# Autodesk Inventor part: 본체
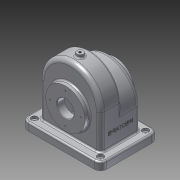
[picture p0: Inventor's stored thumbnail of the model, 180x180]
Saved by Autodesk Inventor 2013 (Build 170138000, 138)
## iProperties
Created: 2017-11
Part Number: 본체
Material: 알루미늄 6061
Document SubType Name: Modeling
Designer: Administrator
Density: 2.71 g/cm^3
Mass: 1117.61 g
Surface Area: 1185.63 cm^2
Volume: 412.401 cm^3
Author: Administrator
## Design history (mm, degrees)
sketch "스케치1"
  geometry: L1 (-58, 0)-(-58, -65); L2 (58, 0)-(58, -65); L3 (-58, -65)-(58, -65); A1 r 58 centre (0, 0) between (58, 0) and (-58, 0); 1 further point
  constraints: 6 end point, 2 point on circle, 2 tangent, 1 centre point, 1 coincident, 1 parallel, 1 vertical
  dimensions: "d0" = 116 diameter of A1; "d2" = 65 distance of L1.start L1.end; "d3" = 65 distance of L2.start L2.end
extrude "돌출1" new body sketch "스케치1" stored distance "d4" = 38; taper "d5" = 0 deg
sketch "스케치2"
  geometry: L1 (-58, -23)-(-58, -65); L2 (58, -23)-(58, -65); L3 (-58, -65)-(58, -65); L4 (-58, -65)-(58, -65) reference; A1 r 58 centre (0, 0) between (58, 0) and (-58, 0) reference; A2 r 58 centre (0, -23) between (58, -23) and (-58, -23); 1 further point
  constraints: 6 end point, 2 point on circle, 2 tangent, 1 centre point, 1 collinear, 1 parallel, 1 perpendicular, 1 vertical, 1 vertical alignment
  dimensions: "d6" = 116 diameter of A2; "d7" = 42 distance of L1.start L1.end
extrude "돌출2" join sketch "스케치2" distance "d8" = 38; taper "d9" = 0 deg
sketch "스케치3"
  geometry: L1 (-58, -65)-(58, -65) reference; C1 r 37.5 at (0, -15); 1 further point
  constraints: 1 centre point, 1 vertical alignment
  dimensions: "d10" = 75 diameter of C1; "d11" = 50 distance from line of C1.centre L1
feature "쉘1" dims "d12" = 5
extrude "돌출3" join sketch "스케치3" distance "d13" = 9; taper "d14" = 0 deg
sketch "스케치4"
  geometry: C1 r 37.5 at (0, -15) reference; 1 further point
extrude "돌출4" join sketch "스케치4" distance "d15" = 10; taper "d16" = 0 deg
sketch "스케치5"
  geometry: C1 r 16 at (0, 0); C2 r 37.5 at (0, 0) reference; 1 further point
  constraints: 1 centre point, 1 concentric
  dimensions: "d17" = 32 diameter of C1
extrude "돌출5" cut sketch "스케치5" stored distance "d18" = 10; taper "d19" = 0 deg
sketch "스케치6"
  geometry: C1 r 16 at (0, 0) reference; 2 further points
  constraints: 1 vertical alignment
  dimensions: "d20" = 29 distance of C1.centre point (0, 29)
hole "구멍1" sketch "스케치6" at (0, 29) diameter "d21" = 2.459; stored, may be unused: countersink angle "d25" = 90 deg, drill point angle "d27" = 118 deg; dims "d22" = 6, "d23" = 4, "d24" = 2, "d26" = 8
node "작업 평면1"
node "작업 평면3"
  node "작업 평면2"
sketch "스케치7"
  geometry: C1 r 6 at (0, 0); 1 further point
  constraints: 1 centre point, 1 coincident
  dimensions: "d32" = 12 diameter of C1
extrude "돌출6" join sketch "스케치7" stored distance "d34" = 10; taper "d35" = 0 deg
sketch "스케치8"
  geometry: 2 further points
  constraints: 1 coincident
hole "구멍2" sketch "스케치8" at (0, 0) diameter "d36" = 4.459; stored, may be unused: countersink angle "d40" = 90 deg, drill point angle "d42" = 118 deg; dims "d37" = 20, "d38" = 4, "d39" = 2, "d41" = 8
sketch "스케치9"
  geometry: L1 (-17, 17)-(133, 17); L2 (133, 17)-(133, -93); L3 (133, -93)-(-17, -93); L4 (-17, -93)-(-17, 17); L5 (0, 0)-(116, 0) reference; L6 (0, -76)-(0, 0) reference; L7 (116, -76)-(116, 0) reference; L8 (116, -76)-(0, -76) reference; L9 (111, -33)-(5, -33) reference; L10 (116, -38)-(0, -38) reference; 1 further point
  constraints: 8 end point, 2 parallel, 1 horizontal, 1 perpendicular
  dimensions: "d43" = 110 distance of L1.end L2.end; "d45" = 150 distance of L1.start L1.end; "d47" = 55 distance between parallel lines of L10 L1; "d48" = 75 distance from line of L4 point (58, -19)
extrude "돌출7" join sketch "스케치9" distance "d49" = 15; taper "d50" = 0 deg
fillet "모깎기1" dims "d51" = 12
sketch "스케치10"
  geometry: A1 r 12 centre (-5, 81) between (-5, 93) and (-17, 81) reference; A2 r 12 centre (121, 81) between (133, 81) and (121, 93) reference; A3 r 12 centre (121, 81) between (133, 81) and (121, 93) reference; A4 r 12 centre (121, -5) between (121, -17) and (133, -5) reference; A5 r 12 centre (121, -5) between (121, -17) and (133, -5) reference; A6 r 12 centre (-5, -5) between (-17, -5) and (-5, -17) reference; 5 further points
  constraints: 4 coincident
hole "구멍3" sketch "스케치10" at (-5, 81), (-5, -5), (121, -5), (121, 81) diameter "d52" = 5; stored, may be unused: countersink angle "d56" = 90 deg, drill point angle "d58" = 118 deg; dims "d53" = 6, "d54" = 12, "d55" = 5, "d57" = 8
fillet "모깎기2" dims "d59" = 3
sketch "스케치11"
  geometry: L1 (111, -8)-(111, -68) reference; L2 (108, -71)-(8, -71) reference; L3 (5, -68)-(5, -8) reference; L4 (8, -5)-(108, -5) reference; L5 (116, -76)-(116, 0) reference; L6 (0, 0)-(116, 0) reference; L7 (0, -76)-(0, 0) reference; L8 (116, -76)-(0, -76) reference; A1 r 3 centre (108, -68) between (108, -71) and (111, -68) reference; A2 r 3 centre (8, -68) between (5, -68) and (8, -71) reference; A3 r 3 centre (8, -8) between (8, -5) and (5, -8) reference; A4 r 3 centre (108, -8) between (111, -8) and (108, -5) reference; 1 further point
extrude "돌출8" join sketch "스케치11" distance "d60" = 15; taper "d61" = 0 deg
fillet "모깎기3" dims "d62" = 8
fillet "모깎기4" dims "d63" = 3
chamfer "모따기1" distance "d64" = 1; stored, may be unused: second distance "d65" = 2, angle "d66" = 45 deg
fillet "모깎기5" dims "d67" = 3
node "작업 평면4"
sketch "스케치12"
  geometry: L1 (73, -18)-(-13, -18) reference; L2 (-8, 62)-(-8, 0) reference; 2 further points
  constraints: 1 other
  dimensions: "d69" = 40 distance from line of L1 point (30, 22); "d70" = 38 distance from line of point (30, 22) L2
feature "엠보싱1" sketch "스케치12" dims "d0" = 116, "d2" = 65, "d3" = 65, "d10" = 75, "d11" = 50, "d71" = 0.5, "d72" = 0
sketch "스케치13"
  geometry: C1 r 37.5 at (0, 0) reference; 2 further points
  constraints: 1 vertical alignment
  dimensions: "d73" = 26 distance of C1.centre point (0, 26)
hole "구멍4" sketch "스케치13" at (0, 26) diameter "d74" = 2.459; stored, may be unused: countersink angle "d78" = 90 deg, drill point angle "d80" = 118 deg; dims "d75" = 6, "d76" = 12, "d77" = 5, "d79" = 8
node "솔리드1"
pattern_circular "원형 패턴1" dims angle "d29" = 360 deg
pattern_circular "원형 패턴2" dims angle "d82" = 360 deg
node "투영된 루프1"
node "투영된 루프2"
node "투영된 루프3"
other parameters: "d31" = 6
